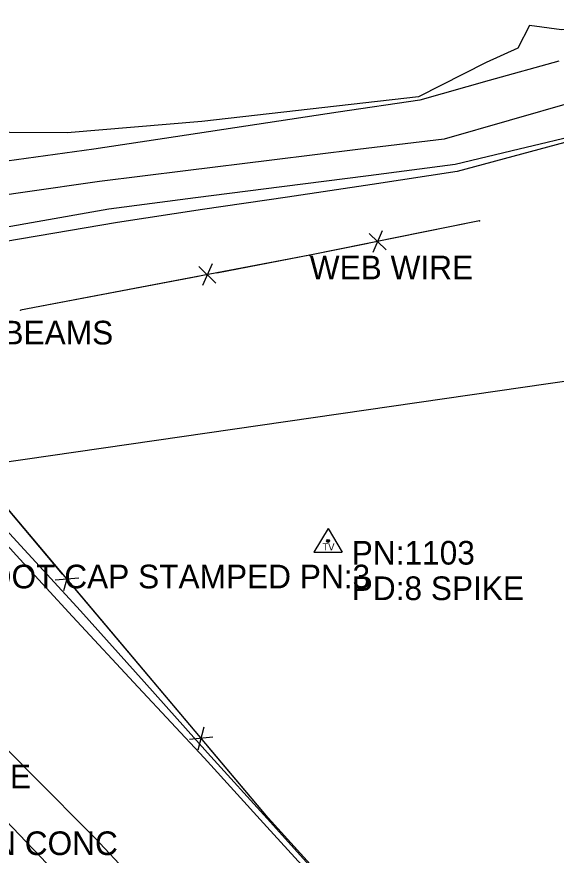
# Model space of a CAD drawing. Extents: x 1660112 to 1662239, y 668919 to 671377.
# Drawn here: x 1661384.3 to 1661498.3, y 670135.7 to 670312.8 of the extents above; entities that cross this region are included whole.
import ezdxf

# ---------------------------------------------------------------- set-up
doc = ezdxf.new("R2010")
doc.units = 0
for name, color, linetype in [('S_BASELINE', 7, 'Continuous'), ('S_DITCHLINE', 7, 'Continuous'), ('S_EDGE_PAVEMENT', 7, 'Continuous'), ('S_FENCE', 7, 'Continuous'), ('S_MSC_PT_SYM', 7, 'Continuous'), ('S_PAVEMENT_CROWN', 7, 'Continuous'), ('S_PRIMARY_CTL_ANNOT', 7, 'Continuous'), ('S_SANITARY_SEWER_ANNOT', 7, 'Continuous'), ('S_SECONDARY_CTL', 7, 'Continuous'), ('S_SECONDARY_CTL_ANNOT', 7, 'Continuous'), ('S_STREAM', 7, 'Continuous'), ('S_SURVEY_TEXT_ANNOT', 7, 'Continuous')]:
    doc.layers.add(name, color=color, linetype=linetype)

msp = doc.modelspace()

# ---------------------------------------------------------------- linework, layer by layer
at = {"layer": 'S_BASELINE'}
msp.add_line((1661335.19, 670212.07), (1662115.18, 670324.54), dxfattribs=at)
at = {"layer": 'S_DITCHLINE'}
for points in [[(1661495.46, 670073.89), (1661482.85, 670088.25), (1661470.25, 670102.6), (1661470.41, 670103.23), (1661460.8, 670115.6), (1661451.19, 670127.97), (1661437.9, 670142.65), (1661424.62, 670157.34), (1661411.2, 670172.34), (1661397.77, 670187.35), (1661386.72, 670199.36), (1661375.66, 670211.37), (1661356.56, 670219.75), (1661346.24, 670231.99), (1661335.91, 670244.22), (1661322, 670253.4)], [(1661494.51, 670072.98), (1661481.63, 670087.01), (1661468.75, 670101.04), (1661468.56, 670102.05), (1661459.49, 670114.59), (1661450.42, 670127.12), (1661437.16, 670141.71), (1661423.9, 670156.29), (1661409.97, 670171.2), (1661396.04, 670186.11), (1661384.96, 670198.23), (1661373.87, 670210.36), (1661354.32, 670219.23), (1661344.06, 670230.9), (1661333.8, 670242.57), (1661320.4, 670253.01)]]:
    msp.add_lwpolyline(points, dxfattribs=at)
at = {"layer": 'S_EDGE_PAVEMENT'}
msp.add_lwpolyline([(1661528.89, 670006.64), (1661525.81, 670010.93), (1661521.19, 670007.06), (1661512.12, 670017.42), (1661503.06, 670027.78), (1661494.14, 670038.45), (1661485.22, 670049.12), (1661475.65, 670058.13), (1661469.7, 670064.69), (1661453.26, 670082.63), (1661441.58, 670095.54), (1661429.9, 670108.45), (1661415.33, 670123.89), (1661400.76, 670139.32), (1661387.62, 670152.61), (1661374.47, 670165.9), (1661358.81, 670181.9), (1661343.14, 670197.9), (1661339.48, 670201.44), (1661329.75, 670211.05), (1661320.02, 670220.65), (1661304.77, 670236.19)], dxfattribs=at)
at = {"layer": 'S_FENCE'}
for p, q in [((1661482.09, 670269.73), (1661446.2, 670262.44)), ((1661461.53, 670267.65), (1661459.54, 670263.06)), ((1661461.53, 670267.65), (1661459.54, 670263.06)), ((1661462.35, 670263.63), (1661458.73, 670267.08)), ((1661462.35, 670263.63), (1661458.73, 670267.08)), ((1661446.2, 670262.44), (1661385.1, 670250.82)), ((1661425.61, 670260.61), (1661423.56, 670256.05)), ((1661425.61, 670260.61), (1661423.56, 670256.05)), ((1661426.38, 670256.59), (1661422.8, 670260.08)), ((1661426.38, 670256.59), (1661422.8, 670260.08)), ((1661437.44, 670143.55), (1661353.95, 670242.57)), ((1661394.26, 670191.59), (1661395.54, 670196.42)), ((1661394.26, 670191.59), (1661395.54, 670196.42)), ((1661397.39, 670194.23), (1661392.41, 670193.78)), ((1661397.39, 670194.23), (1661392.41, 670193.78)), ((1661422.62, 670157.95), (1661423.9, 670162.78)), ((1661422.62, 670157.95), (1661423.9, 670162.78)), ((1661425.75, 670160.59), (1661420.77, 670160.14)), ((1661425.75, 670160.59), (1661420.77, 670160.14)), ((1661463.18, 670115.3), (1661437.44, 670143.55))]:
    msp.add_line(p, q, dxfattribs=at)
for points in [[(1661482.09, 670269.73), (1661462.5, 670265.75)], [(1661482.09, 670269.73), (1661462.5, 670265.75)], [(1661458.58, 670264.96), (1661446.2, 670262.44)], [(1661458.58, 670264.96), (1661446.2, 670262.44)], [(1661446.2, 670262.44), (1661426.55, 670258.7)], [(1661446.2, 670262.44), (1661426.55, 670258.7)], [(1661422.62, 670257.96), (1661385.1, 670250.82)], [(1661422.62, 670257.96), (1661385.1, 670250.82)], [(1661393.97, 670195.1), (1661381.08, 670210.39)], [(1661393.97, 670195.1), (1661381.08, 670210.39)], [(1661421.97, 670161.89), (1661396.19, 670192.47)], [(1661421.97, 670161.89), (1661396.19, 670192.47)], [(1661437.44, 670143.55), (1661424.55, 670158.84)], [(1661437.44, 670143.55), (1661424.55, 670158.84)], [(1661447.01, 670133.04), (1661437.44, 670143.55)], [(1661447.01, 670133.04), (1661437.44, 670143.55)]]:
    msp.add_lwpolyline(points, dxfattribs=at)
at = {"layer": 'S_MSC_PT_SYM'}
for points in [[(1661482.09, 670269.73), (1661482.09, 670269.79), (1661482.09, 670269.73), (1661482.04, 670269.73), (1661482.09, 670269.73), (1661482.09, 670269.68), (1661482.09, 670269.73), (1661482.14, 670269.73)], [(1661446.2, 670262.44), (1661446.2, 670262.49), (1661446.2, 670262.44), (1661446.15, 670262.44), (1661446.2, 670262.44), (1661446.2, 670262.39), (1661446.2, 670262.44), (1661446.25, 670262.44)], [(1661446.2, 670262.37), (1661446.2, 670262.42), (1661446.2, 670262.37), (1661446.15, 670262.37), (1661446.2, 670262.37), (1661446.2, 670262.32), (1661446.2, 670262.37), (1661446.25, 670262.37)], [(1661385.1, 670250.82), (1661385.1, 670250.87), (1661385.1, 670250.82), (1661385.05, 670250.82), (1661385.1, 670250.82), (1661385.1, 670250.77), (1661385.1, 670250.82), (1661385.15, 670250.82)], [(1661437.44, 670143.55), (1661437.44, 670143.6), (1661437.44, 670143.55), (1661437.39, 670143.55), (1661437.44, 670143.55), (1661437.44, 670143.5), (1661437.44, 670143.55), (1661437.49, 670143.55)]]:
    msp.add_lwpolyline(points, dxfattribs=at)
at = {"layer": 'S_PAVEMENT_CROWN'}
msp.add_lwpolyline([(1661518.06, 669996.03), (1661505.4, 670009.31), (1661492.74, 670022.59), (1661480.19, 670036.99), (1661467.64, 670051.39), (1661473.76, 670044.39), (1661461.34, 670057.98), (1661445.4, 670075.38), (1661443.99, 670076.39), (1661432.69, 670088.65), (1661421.39, 670100.9), (1661407.48, 670115.88), (1661393.57, 670130.85), (1661380.41, 670144.59), (1661367.25, 670158.33), (1661351.88, 670174.26), (1661336.51, 670190.18), (1661332.38, 670194.36), (1661323.21, 670203.51), (1661314.05, 670212.66), (1661297.56, 670228.68)], dxfattribs=at)
at = {"layer": 'S_SECONDARY_CTL'}
for p, q in [((1661450.08, 670204.7), (1661447.07, 670199.75)), ((1661450.08, 670204.7), (1661453.03, 670199.75)), ((1661447.07, 670199.75), (1661453.03, 670199.75))]:
    msp.add_line(p, q, dxfattribs=at)
for radius in [0.311, 0.183, 0.103]:
    msp.add_circle((1661450.08, 670202.09), radius, dxfattribs=at)
at = {"layer": 'S_STREAM'}
for points in [[(1661620.34, 670335.21), (1661597.17, 670329.75), (1661574, 670324.29), (1661550.82, 670318.83), (1661527.65, 670313.37), (1661513.53, 670311.73), (1661499.41, 670310.09), (1661492.64, 670311.04), (1661490.16, 670306.19), (1661483.49, 670303.19), (1661469.16, 670295.94), (1661446.28, 670293.35), (1661423.4, 670290.75), (1661409.17, 670289.53), (1661394.93, 670288.3), (1661370.48, 670288.49), (1661352.9, 670285.18), (1661335.31, 670281.88), (1661320.32, 670280.07), (1661305.33, 670278.26)], [(1661622.8, 670312.05), (1661599.9, 670307.69), (1661577, 670303.33), (1661554.1, 670298.98), (1661531.19, 670294.62), (1661517.62, 670291.37), (1661504.05, 670288.12), (1661490.48, 670284.87), (1661476.91, 670281.62), (1661458.63, 670279.27), (1661440.34, 670276.92), (1661422.06, 670274.57), (1661403.77, 670272.22), (1661387.42, 670269.33), (1661371.06, 670266.44), (1661354.71, 670263.56), (1661338.35, 670260.67), (1661316.6, 670255.88), (1661296.46, 670250.86), (1661285.68, 670241.86), (1661274.9, 670232.86), (1661258.9, 670220.78), (1661250.84, 670216.6), (1661237.04, 670210.68)], [(1661623.56, 670311.06), (1661600.76, 670306.67), (1661577.96, 670302.29), (1661555.16, 670297.9), (1661532.36, 670293.52), (1661508.21, 670288.49), (1661492.78, 670284.3), (1661477.36, 670280.12), (1661459.42, 670277.44), (1661441.48, 670274.76), (1661423.55, 670272.09), (1661405.61, 670269.41), (1661388.57, 670266.5), (1661371.54, 670263.59), (1661354.51, 670260.67), (1661337.47, 670257.76), (1661319.37, 670253.79), (1661298.79, 670248.53)], [(1661498.85, 670303.49), (1661484.15, 670299.37), (1661469.46, 670295.26), (1661452.24, 670292.66), (1661435.03, 670290.06), (1661417.81, 670287.47), (1661400.59, 670284.87), (1661384.22, 670282.64), (1661367.85, 670280.4), (1661351.48, 670278.17), (1661335.11, 670275.93), (1661320.77, 670276.1), (1661306.42, 670276.27), (1661294.47, 670269.73), (1661282.53, 670263.19), (1661272.56, 670254.42), (1661262.59, 670245.66), (1661251.64, 670237.74), (1661240.7, 670229.82), (1661218.36, 670218.7)], [(1661502.1, 670294.89), (1661488.35, 670290.94), (1661474.61, 670287), (1661456.4, 670284.77), (1661438.18, 670282.53), (1661419.96, 670280.3), (1661401.75, 670278.07), (1661386.08, 670275.8), (1661370.4, 670273.52), (1661354.73, 670271.25), (1661339.06, 670268.97), (1661325.94, 670268.28), (1661312.82, 670267.6), (1661300.92, 670262.59), (1661289.01, 670257.59), (1661278.51, 670249.41), (1661268, 670241.23), (1661256.41, 670232.4), (1661244.82, 670223.57), (1661232.52, 670217.57)]]:
    msp.add_lwpolyline(points, dxfattribs=at)

# ---------------------------------------------------------------- texts
at = {"layer": 'S_PRIMARY_CTL_ANNOT'}
for s, p in [('PD:STD ARDOT CAP STAMPED PN:3', (1661342.69, 670192.07)), ('PD:CHISELED SQUARE IN CONC', (1661300.89, 670135.71))]:
    msp.add_text(s, height=5, dxfattribs=at).set_placement(p)
at = {"layer": 'S_SANITARY_SEWER_ANNOT'}
msp.add_text('4IN PLASTIC INVERT OF PIPE', height=5, dxfattribs=at).set_placement((1661292.56, 670149.83))
at = {"layer": 'S_SECONDARY_CTL'}
msp.add_text('TV', height=1.5, rotation=360, dxfattribs=at).set_placement((1661448.88, 670200.08))
at = {"layer": 'S_SECONDARY_CTL_ANNOT'}
for s, p in [('PN:1103', (1661455.08, 670197.09)), ('PD:8 SPIKE', (1661455.08, 670189.59))]:
    msp.add_text(s, height=5, dxfattribs=at).set_placement(p)
at = {"layer": 'S_SURVEY_TEXT_ANNOT'}
for s, p in [('WEB WIRE', (1661446.2, 670257.37)), ('CONC DECK WOOD PIERS AND BEAMS', (1661277.99, 670243.61))]:
    msp.add_text(s, height=5, dxfattribs=at).set_placement(p)

doc.saveas('drawing.dxf')
